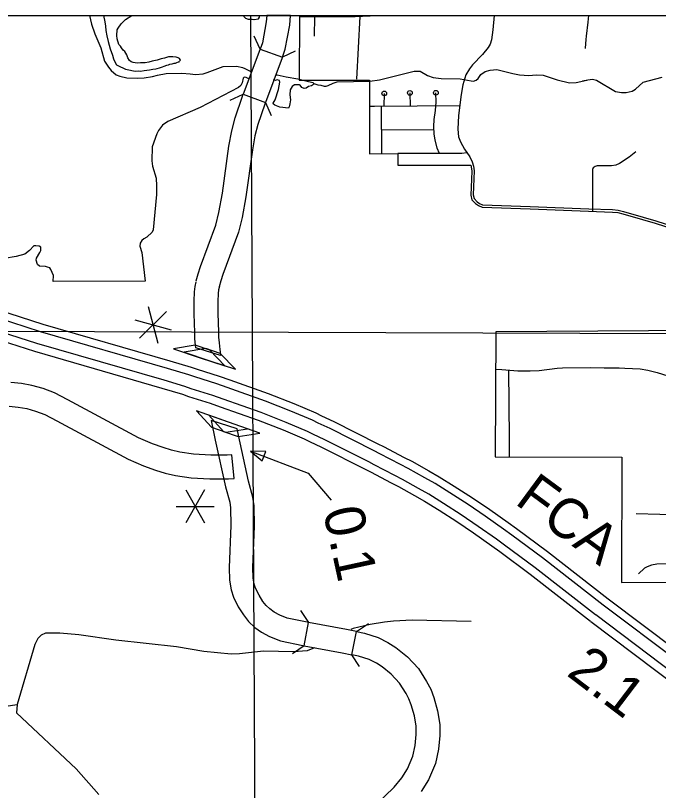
# Model space of a CAD drawing. Extents: x 1374139 to 1377472, y 1168351 to 1170484.
# Drawn here: x 1375233.7 to 1375369.3, y 1169416 to 1169579.4 of the extents above; entities that cross this region are included whole.
import ezdxf

# ---------------------------------------------------------------- set-up
doc = ezdxf.new("R2010")
doc.units = 0
doc.layers.add('26', color=7, linetype='Continuous')
doc.layers.add('Default', color=7, linetype='Continuous')

msp = doc.modelspace()

# ---------------------------------------------------------------- linework, layer by layer
at = {"layer": '26'}
msp.add_lwpolyline([(1375090, 1169579.43), (1376597.43, 1169579.43), (1376597.43, 1168653.79), (1375090, 1168653.79)], close=True, dxfattribs=at)
at = {"layer": 'Default'}
for p, q in [((1375286.72, 1169579.43), (1375286.59, 1169578.1)), ((1375291.74, 1169579.43), (1375286.72, 1169579.43)), ((1375291.55, 1169577.41), (1375291.74, 1169579.43)), ((1375286.59, 1169578.1), (1375285.78, 1169573.65)), ((1375290.62, 1169572.34), (1375291.55, 1169577.41)), ((1375285.78, 1169573.65), (1375285.31, 1169572.36)), ((1375285.31, 1169572.36), (1375290, 1169570.65)), ((1375290, 1169570.65), (1375290.62, 1169572.34)), ((1375281.73, 1169562.83), (1375286.41, 1169561.07)), ((1375206.16, 1169525.07), (1375239.51, 1169514.36)), ((1375239.01, 1169512.73), (1375205.62, 1169523.46)), ((1375261.72, 1169518.06), (1375263.73, 1169510.32)), ((1375265.58, 1169517), (1375259.87, 1169511.39)), ((1375258.87, 1169515.26), (1375266.58, 1169513.13)), ((1375812.86, 1169510.92), (1375090, 1169513.23)), ((1375239.51, 1169514.36), (1375266.26, 1169506.62)), ((1375265.78, 1169504.99), (1375239.01, 1169512.73)), ((1375271.62, 1169509.89), (1375267.07, 1169509.12)), ((1375274.7, 1169508.87), (1375271.62, 1169509.89)), ((1375267.07, 1169509.12), (1375272.48, 1169507.33)), ((1375273.84, 1169509.19), (1375269.28, 1169508.42)), ((1375269.28, 1169508.42), (1375274.7, 1169506.63)), ((1375276.98, 1169507.75), (1375271.76, 1169509.33)), ((1375276.91, 1169508.18), (1375273.84, 1169509.19)), ((1375277.9, 1169505.54), (1375274.7, 1169508.87)), ((1375266.26, 1169506.62), (1375270.77, 1169505.27)), ((1375272.48, 1169507.33), (1375277.9, 1169505.54)), ((1375274.7, 1169506.63), (1375280.11, 1169504.84)), ((1375280.11, 1169504.84), (1375276.91, 1169508.18)), ((1375270.25, 1169503.65), (1375265.78, 1169504.99)), ((1375270.77, 1169505.27), (1375272.07, 1169504.83)), ((1375271.54, 1169503.21), (1375270.25, 1169503.65)), ((1375272.07, 1169504.83), (1375276.71, 1169503.4)), ((1375276.71, 1169503.4), (1375278.95, 1169502.58)), ((1375235.03, 1169501.81), (1375232.77, 1169502.07)), ((1375237.22, 1169501.41), (1375235.03, 1169501.81)), ((1375276.17, 1169501.79), (1375271.54, 1169503.21)), ((1375278.37, 1169500.98), (1375276.17, 1169501.79)), ((1375278.95, 1169502.58), (1375287.02, 1169499.73)), ((1375239.55, 1169500.78), (1375237.22, 1169501.41)), ((1375241.96, 1169499.83), (1375239.55, 1169500.78)), ((1375286.42, 1169498.13), (1375278.37, 1169500.98)), ((1375244.77, 1169498.41), (1375241.96, 1169499.83)), ((1375259.7, 1169490.38), (1375244.77, 1169498.41)), ((1375287.02, 1169499.73), (1375292.44, 1169497.58)), ((1375232.4, 1169497.08), (1375234.29, 1169496.87)), ((1375234.29, 1169496.87), (1375236.11, 1169496.53)), ((1375291.79, 1169496), (1375286.42, 1169498.13)), ((1375292.44, 1169497.58), (1375297.05, 1169495.62)), ((1375236.11, 1169496.53), (1375237.98, 1169496.03)), ((1375237.98, 1169496.03), (1375239.9, 1169495.26)), ((1375239.9, 1169495.26), (1375242.46, 1169493.97)), ((1375277.27, 1169494.15), (1375271.89, 1169496.04)), ((1375271.89, 1169496.04), (1375275.03, 1169492.65)), ((1375296.35, 1169494.07), (1375291.79, 1169496)), ((1375297.05, 1169495.62), (1375298.27, 1169495.03)), ((1375242.46, 1169493.97), (1375257.53, 1169485.87)), ((1375279.86, 1169493.24), (1375274.48, 1169495.12)), ((1375274.48, 1169495.12), (1375277.61, 1169491.74)), ((1375280.45, 1169492.3), (1375274.96, 1169494.04)), ((1375282.66, 1169492.27), (1375277.27, 1169494.15)), ((1375297.55, 1169493.49), (1375296.35, 1169494.07)), ((1375298.27, 1169495.03), (1375300.83, 1169493.84)), ((1375300.83, 1169493.84), (1375310.14, 1169489.13)), ((1375275.03, 1169492.65), (1375278.09, 1169491.58)), ((1375278.09, 1169491.58), (1375282.66, 1169492.27)), ((1375285.24, 1169491.36), (1375279.86, 1169493.24)), ((1375300.09, 1169492.31), (1375297.55, 1169493.49)), ((1375309.37, 1169487.62), (1375300.09, 1169492.31)), ((1375262.62, 1169489.14), (1375259.7, 1169490.38)), ((1375277.61, 1169491.74), (1375280.67, 1169490.67)), ((1375280.67, 1169490.67), (1375285.24, 1169491.36)), ((1375264.85, 1169488.3), (1375262.62, 1169489.14)), ((1375310.14, 1169489.13), (1375311.34, 1169488.52)), ((1375266.61, 1169487.76), (1375264.85, 1169488.3)), ((1375268.38, 1169487.34), (1375266.61, 1169487.76)), ((1375271.25, 1169486.93), (1375268.38, 1169487.34)), ((1375310.55, 1169487.01), (1375309.37, 1169487.62)), ((1375314.87, 1169484.73), (1375310.55, 1169487.01)), ((1375311.34, 1169488.52), (1375315.64, 1169486.25)), ((1375257.53, 1169485.87), (1375260.75, 1169484.5)), ((1375274.89, 1169486.75), (1375271.25, 1169486.93)), ((1375277.35, 1169486.71), (1375274.89, 1169486.75)), ((1375278.37, 1169486.71), (1375277.35, 1169486.71)), ((1375279.38, 1169486.81), (1375278.37, 1169486.71)), ((1375279.87, 1169481.83), (1375279.38, 1169486.81)), ((1375315.64, 1169486.25), (1375317.31, 1169485.43)), ((1375317.31, 1169485.43), (1375320.85, 1169483.43)), ((1375260.75, 1169484.5), (1375263.23, 1169483.57)), ((1375316.52, 1169483.92), (1375314.87, 1169484.73)), ((1375320.01, 1169481.96), (1375316.52, 1169483.92)), ((1375263.23, 1169483.57), (1375265.3, 1169482.94)), ((1375265.3, 1169482.94), (1375267.44, 1169482.43)), ((1375267.44, 1169482.43), (1375270.77, 1169481.95)), ((1375320.85, 1169483.43), (1375323.06, 1169482.17)), ((1375323.06, 1169482.17), (1375326.22, 1169480.2)), ((1375270.77, 1169481.95), (1375274.72, 1169481.76)), ((1375274.72, 1169481.76), (1375277.3, 1169481.71)), ((1375277.3, 1169481.71), (1375278.61, 1169481.71)), ((1375278.61, 1169481.71), (1375279.87, 1169481.83)), ((1375322.18, 1169480.71), (1375320.01, 1169481.96)), ((1375325.32, 1169478.76), (1375322.18, 1169480.71)), ((1375273.62, 1169479.39), (1375269.62, 1169472.46)), ((1375269.62, 1169479.39), (1375273.62, 1169472.46)), ((1375326.22, 1169480.2), (1375330.08, 1169477.75)), ((1375329.15, 1169476.33), (1375325.32, 1169478.76)), ((1375330.08, 1169477.75), (1375333.74, 1169475.24)), ((1375267.62, 1169475.92), (1375275.62, 1169475.92)), ((1375332.77, 1169473.85), (1375329.15, 1169476.33)), ((1375333.74, 1169475.24), (1375337.61, 1169472.5)), ((1375336.62, 1169471.11), (1375332.77, 1169473.85)), ((1375337.61, 1169472.5), (1375339.38, 1169471.24)), ((1375338.37, 1169469.86), (1375336.62, 1169471.11)), ((1375339.38, 1169471.24), (1375345.87, 1169466.39)), ((1375344.84, 1169465.04), (1375338.37, 1169469.86)), ((1375345.87, 1169466.39), (1375358.64, 1169456.45)), ((1375357.61, 1169455.1), (1375344.84, 1169465.04)), ((1375358.64, 1169456.45), (1375386.44, 1169435.46)), ((1375385.39, 1169434.13), (1375357.61, 1169455.1)), ((1375294.62, 1169446.54), (1375295.54, 1169451.46)), ((1375304.62, 1169444.64), (1375305.63, 1169449.54))]:
    msp.add_line(p, q, dxfattribs=at)
for points in [[(1375249.31, 1169579.43), (1375249.76, 1169577.63), (1375250.48, 1169575.55), (1375251.72, 1169572.62), (1375252.54, 1169569.81), (1375253.34, 1169568.5), (1375253.93, 1169567.8), (1375255, 1169566.94), (1375255.77, 1169566.61), (1375257.2, 1169566.25), (1375259.42, 1169566.18), (1375260.88, 1169566.26), (1375262.61, 1169566.57), (1375263.65, 1169566.88), (1375265.5, 1169567.19)], [(1375252.3, 1169579.43), (1375252.58, 1169578.09), (1375252.74, 1169577.15), (1375252.81, 1169576.29), (1375253.03, 1169575.15), (1375253.29, 1169573.91), (1375253.68, 1169572.39), (1375254.2, 1169571.07), (1375254.41, 1169570.27), (1375254.66, 1169569.64), (1375255.01, 1169569.04), (1375255.46, 1169568.79), (1375255.86, 1169568.57), (1375256.34, 1169568.38), (1375256.91, 1169568.13), (1375257.29, 1169568.02), (1375258.95, 1169567.68), (1375259.77, 1169567.74), (1375260.11, 1169567.72), (1375260.85, 1169567.86), (1375261.45, 1169567.91), (1375261.99, 1169567.94), (1375262.72, 1169568.09), (1375263.32, 1169568.18), (1375263.6, 1169568.22), (1375264.12, 1169568.39), (1375264.76, 1169568.61), (1375265.11, 1169568.73), (1375265.63, 1169568.92), (1375266.03, 1169569.03), (1375266.29, 1169569.13), (1375266.74, 1169569.26), (1375267.2, 1169569.39), (1375267.46, 1169569.41), (1375267.74, 1169569.5), (1375268.12, 1169569.65), (1375268.22, 1169569.69), (1375268.33, 1169569.83), (1375268.47, 1169569.95), (1375268.53, 1169570.08), (1375268.49, 1169570.13), (1375268.33, 1169570.35), (1375268.06, 1169570.49), (1375267.64, 1169570.64), (1375266.94, 1169570.73), (1375265.98, 1169570.71), (1375265.16, 1169570.46), (1375264.43, 1169570.27), (1375263.63, 1169570.01), (1375262.56, 1169569.77)], [(1375262.56, 1169569.77), (1375261.86, 1169569.6), (1375261.08, 1169569.47), (1375260.06, 1169569.45), (1375259.52, 1169569.4), (1375258.96, 1169569.43), (1375258.56, 1169569.5), (1375258.1, 1169569.68), (1375257.8, 1169569.93), (1375257.41, 1169570.51), (1375257.18, 1169571.12), (1375256.78, 1169571.84), (1375256.46, 1169572.12), (1375256.11, 1169572.61), (1375255.89, 1169572.95), (1375255.54, 1169573.28), (1375255.2, 1169574.48), (1375255.13, 1169575.18), (1375255.21, 1169576.37), (1375255.36, 1169576.79), (1375256.03, 1169577.67), (1375256.93, 1169578.59), (1375258.27, 1169579.43)], [(1375281.83, 1169579.43), (1375281.83, 1169579.4), (1375281.91, 1169579.23), (1375282, 1169579.08), (1375282.07, 1169578.99), (1375282.26, 1169578.84), (1375282.42, 1169578.76), (1375282.56, 1169578.72), (1375282.79, 1169578.67), (1375283.05, 1169578.65), (1375283.31, 1169578.66), (1375283.63, 1169578.64), (1375283.95, 1169578.61), (1375284.08, 1169578.61)], [(1375283.31, 1169579.43), (1375284.22, 1169407.21)], [(1375284.08, 1169578.61), (1375284.96, 1169578.7), (1375285.17, 1169579.08), (1375285.12, 1169579.43)], [(1375293.6, 1169579.43), (1375293.53, 1169565.82), (1375308.34, 1169565.81), (1375308.34, 1169550.29), (1375314.35, 1169550.31), (1375314.35, 1169547.89), (1375329.7, 1169547.88), (1375329.8, 1169547.54), (1375329.94, 1169546.62), (1375329.75, 1169541.55), (1375329.97, 1169540.58), (1375330.7, 1169539.76), (1375331.34, 1169539.35), (1375332.09, 1169539.03), (1375342.24, 1169538.67), (1375354.55, 1169538.16)], [(1375293.6, 1169579.16), (1375305.35, 1169579.2), (1375310.05, 1169579.43)], [(1375293.64, 1169579.43), (1375293.6, 1169579.16)], [(1375296.76, 1169579.17), (1375296.69, 1169575.06)], [(1375306.33, 1169579.24), (1375305.65, 1169565.97)], [(1375307.72, 1169579.31), (1375307.76, 1169579.43)], [(1375334.62, 1169579.43), (1375334.39, 1169576.42), (1375334.1, 1169574.27), (1375333.81, 1169573.35), (1375333.38, 1169572.65), (1375332.17, 1169571.21), (1375330.07, 1169569.03), (1375329.41, 1169568.17), (1375328.7, 1169566.91), (1375328.02, 1169564.82), (1375327.71, 1169562.75), (1375327.15, 1169558.35), (1375326.98, 1169555.45), (1375327.13, 1169553.81), (1375327.57, 1169552.76), (1375328.37, 1169551.24), (1375329.49, 1169549.63), (1375330, 1169548.59), (1375330.28, 1169547.65), (1375330.45, 1169546.66), (1375330.25, 1169541.6), (1375330.43, 1169540.82), (1375331.03, 1169540.15), (1375331.57, 1169539.79), (1375332.2, 1169539.53), (1375342.26, 1169539.17), (1375354.57, 1169538.66)], [(1375328.87, 1169579.43), (1375334.62, 1169579.38)], [(1375354.54, 1169579.43), (1375354.46, 1169578.71), (1375354.38, 1169577.99), (1375354.06, 1169575.08), (1375354, 1169574.37), (1375353.82, 1169572.51), (1375353.82, 1169572.44)], [(1375285.31, 1169572.36), (1375284.04, 1169575.08)], [(1375285.31, 1169572.36), (1375285.26, 1169572.22), (1375281.73, 1169562.83)], [(1375290, 1169570.65), (1375289.94, 1169570.49), (1375286.41, 1169561.07)], [(1375292.72, 1169571.91), (1375290, 1169570.65)], [(1375274.16, 1169567.39), (1375277.54, 1169568.64), (1375280.4, 1169568.71), (1375281.63, 1169568.43), (1375282.09, 1169568.22), (1375283.49, 1169567.52)], [(1375265.5, 1169567.19), (1375268.84, 1169567.26), (1375270.54, 1169567.11)], [(1375265.5, 1169567.19), (1375268.84, 1169567.26), (1375270.54, 1169567.11)], [(1375270.54, 1169567.11), (1375271.71, 1169567.02), (1375273.3, 1169567.11), (1375274.16, 1169567.39)], [(1375296.62, 1169565.07), (1375297.45, 1169564.84), (1375298.12, 1169564.71), (1375298.8, 1169564.53), (1375299.23, 1169564.53), (1375299.64, 1169564.65), (1375300.7, 1169565.19), (1375301.57, 1169565.47), (1375308.41, 1169565.61), (1375310.47, 1169565.88), (1375317.75, 1169567.7), (1375319.07, 1169567.67), (1375320.59, 1169566.75), (1375321.82, 1169566.36), (1375323.45, 1169566.12), (1375327.51, 1169566.08), (1375329.82, 1169565.62), (1375330.3, 1169565.61), (1375330.82, 1169565.76), (1375331.25, 1169566.17), (1375331.83, 1169566.97), (1375332.73, 1169567.59), (1375333.81, 1169567.92), (1375335.2, 1169568.07), (1375338.55, 1169567.2), (1375339.99, 1169566.91), (1375341.98, 1169566.8), (1375343.53, 1169566.92), (1375344.94, 1169566.83), (1375347.92, 1169565.89), (1375350.54, 1169565.25), (1375351.92, 1169565.28), (1375354.15, 1169565.81)], [(1375282.94, 1169566.05), (1375282.36, 1169566.37), (1375281.94, 1169566.42), (1375281.71, 1169566.19), (1375281.51, 1169565.24), (1375281.21, 1169564.68), (1375280.76, 1169564.26), (1375272.67, 1169560.01)], [(1375293.6, 1169564.83), (1375292.56, 1169564.8), (1375292.05, 1169564.48), (1375291.63, 1169563.73), (1375291.58, 1169562.67), (1375291.68, 1169561.67), (1375291.58, 1169560.81), (1375291.43, 1169560.16), (1375291.27, 1169559.9), (1375289.49, 1169560.11), (1375288.43, 1169560.51), (1375288.13, 1169560.71), (1375288.08, 1169560.91), (1375288.51, 1169561.62), (1375289.16, 1169563.85), (1375289.49, 1169565.39), (1375289.41, 1169565.74), (1375288.91, 1169565.84), (1375288.46, 1169565.72), (1375288.04, 1169565.76)], [(1375288.61, 1169566.93), (1375288.89, 1169566.92), (1375290.78, 1169566.51), (1375293.26, 1169566.05), (1375294.92, 1169565.63), (1375296.41, 1169565.29), (1375296.62, 1169565.07), (1375296.57, 1169564.88), (1375296.12, 1169564.59), (1375295.48, 1169564.43), (1375295.01, 1169564.11), (1375294.57, 1169564.04), (1375294.13, 1169564.27), (1375293.73, 1169564.76), (1375293.6, 1169564.83)], [(1375353.29, 1169565.64), (1375354.38, 1169565.89), (1375355.34, 1169565.98), (1375356.19, 1169565.82), (1375360.25, 1169563.41), (1375361.49, 1169563.16), (1375362.47, 1169563.19), (1375363.71, 1169563.5), (1375364.4, 1169563.92), (1375366.02, 1169565.34), (1375370.06, 1169566.42)], [(1375271.84, 1169523.47), (1375272.22, 1169524.94), (1375272.75, 1169526.48), (1375275.94, 1169535.2), (1375276.6, 1169537.87), (1375277.35, 1169541.99), (1375278.74, 1169551.88), (1375279.33, 1169555.13), (1375280.03, 1169557.85), (1375281.59, 1169562.44), (1375281.73, 1169562.83)], [(1375279, 1169561.59), (1375281.73, 1169562.83)], [(1375311.48, 1169563), (1375311.4, 1169560.28)], [(1375316.88, 1169563.11), (1375316.91, 1169560.3)], [(1375323.13, 1169550.32), (1375322.62, 1169551.45), (1375322.21, 1169553.23), (1375322.03, 1169554.43), (1375321.93, 1169556.04), (1375322.01, 1169557.47), (1375322.29, 1169559.38), (1375322.39, 1169561.14), (1375322.36, 1169563.13)], [(1375286.41, 1169561.07), (1375286.3, 1169560.76), (1375284.83, 1169556.42), (1375284.21, 1169554.06), (1375283.68, 1169551.09), (1375282.29, 1169541.19), (1375281.49, 1169536.82), (1375280.73, 1169533.74), (1375277.47, 1169524.81), (1375277.02, 1169523.5), (1375276.68, 1169522.21)], [(1375286.41, 1169561.07), (1375287.66, 1169558.34)], [(1375272.67, 1169560.01), (1375265.89, 1169557.06), (1375264.76, 1169556.28), (1375263.92, 1169555.21), (1375263.53, 1169554.44), (1375262.57, 1169551.74), (1375262.45, 1169548.79), (1375262.63, 1169547.64), (1375263.37, 1169545.14), (1375263.49, 1169543.54), (1375263.44, 1169541.68), (1375262.73, 1169534.23), (1375262.56, 1169533.73), (1375261.43, 1169532.67), (1375260.78, 1169532.36), (1375260.4, 1169531.95), (1375260.01, 1169531.39), (1375259.94, 1169530.77), (1375260.38, 1169529.45), (1375261.06, 1169523.41), (1375241.68, 1169523.36), (1375241.77, 1169524.61), (1375241.21, 1169525.88), (1375240.95, 1169526.22), (1375240.52, 1169526.37)], [(1375327.4, 1169560.35), (1375309.39, 1169560.27), (1375308.34, 1169560.25)], [(1375310.82, 1169560.28), (1375310.86, 1169550.3)], [(1375310.84, 1169555.38), (1375321.97, 1169555.35)], [(1375328.88, 1169550.45), (1375327.82, 1169550.36), (1375326.24, 1169550.33), (1375314.35, 1169550.31)], [(1375364.53, 1169550.65), (1375363.1, 1169549.57), (1375361.06, 1169548.22), (1375360.32, 1169547.89), (1375359.4, 1169547.73), (1375356.37, 1169547.71), (1375355.92, 1169547.62), (1375355.54, 1169547.33), (1375355.36, 1169546.95), (1375355.34, 1169546.45), (1375355.38, 1169538.64), (1375355.36, 1169538.14)], [(1375354.55, 1169538.16), (1375359.57, 1169537.99), (1375360.71, 1169537.88), (1375361.78, 1169537.64), (1375365.88, 1169536.41), (1375368.58, 1169535.65), (1375374.89, 1169533.61), (1375377.3, 1169532.82), (1375379.88, 1169532.31), (1375382.57, 1169531.85), (1375384.14, 1169531.67), (1375385.84, 1169531.43), (1375386.3, 1169531.33), (1375386.63, 1169531.27), (1375387.13, 1169531), (1375387.53, 1169530.57), (1375387.66, 1169530.07), (1375387.98, 1169515.25), (1375388.64, 1169514.47)], [(1375354.57, 1169538.66), (1375359.6, 1169538.49), (1375360.79, 1169538.37), (1375361.91, 1169538.13), (1375366.02, 1169536.89), (1375368.72, 1169536.13), (1375375.04, 1169534.08), (1375377.43, 1169533.3), (1375379.98, 1169532.8), (1375382.64, 1169532.34), (1375384.21, 1169532.17), (1375385.93, 1169531.92), (1375386.4, 1169531.82), (1375386.79, 1169531.74), (1375387.44, 1169531.4), (1375387.98, 1169530.82), (1375388.16, 1169530.14), (1375388.48, 1169515.44), (1375389.27, 1169514.5), (1375390.54, 1169513.3), (1375391.35, 1169512.8)], [(1375240.52, 1169526.37), (1375240.1, 1169526.49), (1375238.8, 1169526.55), (1375238.38, 1169526.94), (1375238.08, 1169527.86), (1375238.2, 1169528.26), (1375238.9, 1169529.42), (1375239.07, 1169529.86), (1375239.06, 1169530.6), (1375238.74, 1169530.76), (1375238.04, 1169530.89), (1375237.64, 1169530.88), (1375236.69, 1169529.84), (1375235.72, 1169529.07), (1375233.89, 1169528.6), (1375228.92, 1169527.77), (1375226.29, 1169527.43), (1375220.01, 1169527.03), (1375218.36, 1169526.71)], [(1375271.76, 1169509.33), (1375271.7, 1169509.89), (1375271.57, 1169511.24), (1375271.53, 1169512.56), (1375271.43, 1169516.49), (1375271.4, 1169519.22), (1375271.51, 1169521.13), (1375271.61, 1169522.27), (1375271.8, 1169523.3)], [(1375276.72, 1169522.38), (1375276.57, 1169521.6), (1375276.5, 1169520.78), (1375276.41, 1169519.09), (1375276.43, 1169516.57), (1375276.53, 1169512.7), (1375276.56, 1169511.57), (1375276.68, 1169510.38), (1375276.82, 1169508.98), (1375276.94, 1169507.97), (1375276.98, 1169507.75)], [(1375356.02, 1169453.04), (1375343.27, 1169462.97), (1375336.84, 1169467.76), (1375335.12, 1169468.99), (1375331.28, 1169471.71), (1375327.71, 1169474.16), (1375323.94, 1169476.56), (1375320.85, 1169478.47), (1375318.72, 1169479.7), (1375315.3, 1169481.62), (1375313.69, 1169482.42), (1375309.35, 1169484.71), (1375308.19, 1169485.3), (1375298.96, 1169489.97), (1375296.44, 1169491.14), (1375295.28, 1169491.7), (1375290.8, 1169493.6), (1375285.51, 1169495.7), (1375277.49, 1169498.53), (1375275.34, 1169499.32), (1375270.74, 1169500.74), (1375269.46, 1169501.17), (1375265.05, 1169502.5), (1375238.25, 1169510.24), (1375204.84, 1169520.98)], [(1375204.32, 1169519.36), (1375237.76, 1169508.62), (1375264.57, 1169500.87), (1375268.94, 1169499.55), (1375270.22, 1169499.12), (1375274.79, 1169497.71), (1375276.92, 1169496.93), (1375284.91, 1169494.11), (1375290.16, 1169492.03), (1375294.58, 1169490.15), (1375295.71, 1169489.61), (1375298.22, 1169488.44), (1375307.42, 1169483.79), (1375308.57, 1169483.2), (1375312.91, 1169480.9), (1375314.51, 1169480.12), (1375317.88, 1169478.22), (1375319.98, 1169477.02), (1375323.03, 1169475.12), (1375326.78, 1169472.74), (1375330.31, 1169470.32), (1375334.13, 1169467.61), (1375335.84, 1169466.39), (1375342.24, 1169461.62), (1375354.98, 1169451.7)], [(1375388.64, 1169514.41), (1375388.65, 1169513.06), (1375335.01, 1169512.74), (1375334.82, 1169486.36), (1375361.57, 1169486.32), (1375361.46, 1169459.86), (1375388.13, 1169459.91), (1375409.38, 1169459.76)], [(1375334.96, 1169504.83), (1375336.29, 1169504.79), (1375339.65, 1169504.52), (1375342.26, 1169504.49), (1375344.1, 1169504.59), (1375347.9, 1169505.05), (1375349.03, 1169505.13), (1375355.03, 1169505.21), (1375357.86, 1169505.12), (1375360.98, 1169505.12), (1375362.18, 1169505.07), (1375365.44, 1169504.93), (1375367.06, 1169504.66), (1375369.01, 1169504.15), (1375376.15, 1169501.89), (1375378.14, 1169501.36), (1375379.72, 1169500.96), (1375381.75, 1169500.87), (1375383.32, 1169500.99), (1375384.8, 1169501.04), (1375387.83, 1169500.99)], [(1375337.66, 1169504.68), (1375337.77, 1169490.15), (1375337.79, 1169486.36)], [(1375274.96, 1169494.04), (1375275.86, 1169489.88), (1375277.99, 1169480.02), (1375278.9, 1169476.78), (1375279.09, 1169475.58), (1375279.12, 1169471.87), (1375278.75, 1169463.02), (1375278.88, 1169460.33), (1375279.2, 1169458.32), (1375279.69, 1169456.81), (1375280.71, 1169454.77), (1375281.79, 1169453.03), (1375282.89, 1169451.63), (1375284.22, 1169450.41), (1375285.58, 1169449.43), (1375287.3, 1169448.45), (1375289.63, 1169447.54), (1375294.28, 1169446.61), (1375294.62, 1169446.54)], [(1375295.54, 1169451.46), (1375295.23, 1169451.52), (1375291.04, 1169452.35), (1375289.46, 1169452.97), (1375288.29, 1169453.64), (1375287.38, 1169454.3), (1375286.57, 1169455.04), (1375285.89, 1169455.89), (1375285.08, 1169457.2), (1375284.33, 1169458.7), (1375284.08, 1169459.49), (1375283.86, 1169460.85), (1375283.75, 1169463.04), (1375284.12, 1169471.78), (1375284.08, 1169476), (1375283.79, 1169477.85), (1375282.85, 1169481.22), (1375280.74, 1169490.94), (1375280.45, 1169492.3)], [(1375283.26, 1169487.59), (1375295.47, 1169482.94), (1375300.29, 1169477.26)], [(1375375.28, 1169483.95), (1375374.94, 1169480.6), (1375374.56, 1169473.59), (1375374.36, 1169465.28), (1375374.27, 1169464.6), (1375373.93, 1169464.16), (1375373.59, 1169463.92), (1375373.11, 1169463.78), (1375372.14, 1169463.78), (1375368.95, 1169463.73), (1375367.84, 1169463.54), (1375366.87, 1169463.2), (1375366.3, 1169462.86), (1375365.09, 1169461.7)], [(1375374.58, 1169474.07), (1375364.6, 1169474.36)], [(1375293.84, 1169453.93), (1375295.54, 1169451.46)], [(1375383.77, 1169432.1), (1375356.04, 1169453.03)], [(1375305.63, 1169449.54), (1375303.53, 1169449.97), (1375295.54, 1169451.46)], [(1375329.77, 1169451.68), (1375317.38, 1169451.91), (1375313.43, 1169451.73), (1375311.55, 1169451.51), (1375308.52, 1169451.03), (1375304.94, 1169450.17), (1375304.44, 1169449.95)], [(1375305.63, 1169449.54), (1375308.13, 1169451.19)], [(1375355.01, 1169451.67), (1375382.7, 1169430.77), (1375383.1, 1169431.26), (1375383.77, 1169432.1)], [(1375305.63, 1169449.54), (1375307.31, 1169449.19), (1375310.17, 1169448.28), (1375312.25, 1169447.22), (1375313.94, 1169446.19), (1375316.36, 1169444.22), (1375318.69, 1169441.71), (1375320.39, 1169439), (1375321.26, 1169437.41), (1375321.91, 1169435.61), (1375322.73, 1169432.82), (1375323.18, 1169429.95), (1375323.18, 1169427.62), (1375322.92, 1169424.72), (1375322.26, 1169421.7), (1375320.78, 1169418.25), (1375319.25, 1169415.79)], [(1375296.8, 1169446.09), (1375295.2, 1169445.43), (1375292.38, 1169445.22), (1375286.02, 1169445.4), (1375280.97, 1169444.8), (1375279.23, 1169444.78), (1375273.44, 1169445.29), (1375267.68, 1169446.27), (1375254.87, 1169447.68), (1375247.07, 1169448.86), (1375243.1, 1169449.16), (1375240.06, 1169449.18), (1375239.17, 1169448.74), (1375238.45, 1169448.05), (1375237.85, 1169446.77), (1375234.11, 1169434.11)], [(1375294.62, 1169446.54), (1375292.15, 1169444.85)], [(1375294.62, 1169446.54), (1375302.57, 1169445.06), (1375304.62, 1169444.64)], [(1375306.27, 1169442.14), (1375304.62, 1169444.64)], [(1375309.68, 1169412.99), (1375313.57, 1169416.69), (1375315.16, 1169418.69), (1375316.34, 1169420.57), (1375317.47, 1169423.22), (1375317.97, 1169425.48), (1375318.18, 1169427.84), (1375318.18, 1169429.56), (1375317.84, 1169431.73), (1375317.16, 1169434.06), (1375316.69, 1169435.35), (1375316.08, 1169436.46), (1375314.7, 1169438.65), (1375312.93, 1169440.57), (1375311.06, 1169442.1), (1375309.81, 1169442.85), (1375308.26, 1169443.64), (1375306.05, 1169444.35), (1375304.62, 1169444.64)], [(1375229.71, 1169433.48), (1375234.11, 1169434.11), (1375233.93, 1169432.4), (1375246.53, 1169420.57), (1375251.3, 1169415.14)]]:
    msp.add_lwpolyline(points, dxfattribs=at)
msp.add_lwpolyline([(1375285.75, 1169485.55), (1375286.48, 1169487.46), (1375283.26, 1169487.59)], close=True, dxfattribs=at)
for centre in [(1375311.48, 1169563), (1375316.88, 1169563.11), (1375322.36, 1169563.13)]:
    msp.add_circle(centre, 0.5, dxfattribs=at)

# ---------------------------------------------------------------- texts
for s, rotation, p in [('FCA', 323.624, (1375338.77, 1169476.6)), ('0.1', 282.2525, (1375298.53, 1169475)), ('2.1', 322.756, (1375349.68, 1169440.44))]:
    msp.add_text(s, height=8.448, rotation=rotation, dxfattribs=at).set_placement(p)

doc.saveas('drawing.dxf')
